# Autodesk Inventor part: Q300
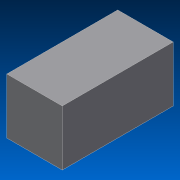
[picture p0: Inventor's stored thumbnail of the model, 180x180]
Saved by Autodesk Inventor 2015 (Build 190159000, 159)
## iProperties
Created: 2017-11
Part Number: Q300
Material: Všeobecné
Document SubType Name: Modeling
Designer: navara
Mass: 2 g
Surface Area: 10 cm^2
Volume: 2 cm^3
Density: 1 g/cm^3
Appearance: Výchozí
Title: 998877
Author: navara
Last Saved By: navara
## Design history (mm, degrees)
sketch "Náčrt1"
  geometry: L1 (-5, 5)-(5, 5); L2 (5, 5)-(5, -5); L3 (5, -5)-(-5, -5); L4 (-5, -5)-(-5, 5); L5 (-5, 5)-(5, -5); L6 (5, 5)-(-5, -5); 1 further point
  constraints: 12 end point, 2 midpoint, 2 parallel, 1 horizontal, 1 perpendicular
  dimensions: "d0" = 10 distance of L2.end L3.end; "d1" = 10 distance of L1.end L2.end
extrude "Vysunutí1" new body sketch "Náčrt1" distance "d2" = 20; taper "d3" = 0 deg
node "Těleso1"
